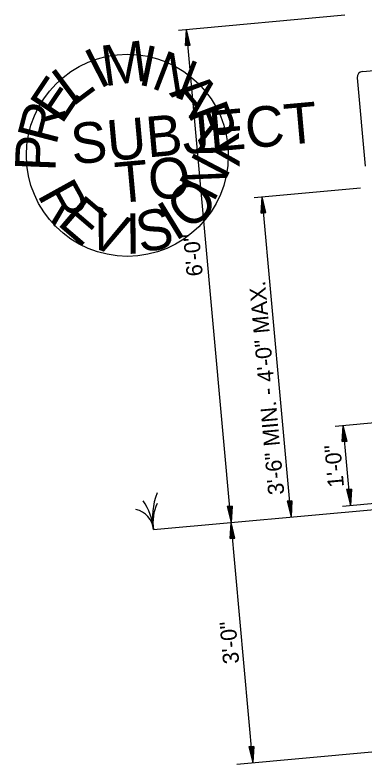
# Model space of a CAD drawing. Extents: x 1277218 to 1279252, y 196860 to 197529.
# Drawn here: x 1278236.5 to 1278336.3, y 197239.4 to 197453.2 of the extents above; entities that cross this region are included whole.
import ezdxf

# ---------------------------------------------------------------- set-up
doc = ezdxf.new("R2010")
doc.units = 0
doc.layers.add('R_Border PE', color=7, linetype='Continuous')
doc.layers.add('R_Point Sym', color=7, linetype='Continuous')

msp = doc.modelspace()

# ---------------------------------------------------------------- linework, layer by layer
at = {"layer": 'R_Border PE'}
msp.add_circle((1278268.61, 197413.17), 28.85, dxfattribs=at)
at = {"layer": 'R_Point Sym'}
for p, q in [((1278283.2, 197448.93), (1278330.8, 197453.24)), ((1278285.22, 197444.5), (1278285.49, 197449.13)), ((1278285.33, 197444.51), (1278285.56, 197448.37)), ((1278285.45, 197444.52), (1278285.63, 197447.58)), ((1278298.25, 197308.34), (1278285.49, 197449.13)), ((1278286.59, 197444.62), (1278285.49, 197449.13)), ((1278286.48, 197444.61), (1278285.56, 197448.37)), ((1278286.36, 197444.6), (1278285.63, 197447.58)), ((1278285.56, 197444.53), (1278285.7, 197446.82)), ((1278285.68, 197444.54), (1278285.77, 197446.05)), ((1278286.24, 197444.59), (1278285.7, 197446.82)), ((1278286.13, 197444.58), (1278285.77, 197446.05)), ((1278285.22, 197444.5), (1278286.59, 197444.62)), ((1278285.8, 197444.55), (1278285.84, 197445.28)), ((1278286.01, 197444.57), (1278285.84, 197445.28)), ((1278335.79, 197437.1), (1278349.6, 197438.36)), ((1278334.27, 197435.29), (1278336.56, 197410.05)), ((1278304.82, 197401.11), (1278335.28, 197403.87)), ((1278306.83, 197396.69), (1278307.11, 197401.32)), ((1278306.95, 197396.7), (1278307.17, 197400.56)), ((1278315.39, 197309.9), (1278307.11, 197401.32)), ((1278308.2, 197396.81), (1278307.11, 197401.32)), ((1278308.09, 197396.8), (1278307.17, 197400.56)), ((1278307.06, 197396.71), (1278307.25, 197399.77)), ((1278307.18, 197396.72), (1278307.31, 197399.01)), ((1278307.97, 197396.79), (1278307.25, 197399.77)), ((1278307.86, 197396.78), (1278307.31, 197399.01)), ((1278306.83, 197396.69), (1278308.2, 197396.81)), ((1278307.3, 197396.73), (1278307.38, 197398.24)), ((1278307.74, 197396.77), (1278307.38, 197398.24)), ((1278307.41, 197396.74), (1278307.45, 197397.47)), ((1278307.63, 197396.76), (1278307.45, 197397.47)), ((1278328.02, 197335.85), (1278341.33, 197337.06)), ((1278330.03, 197331.42), (1278330.3, 197336.06)), ((1278330.14, 197331.43), (1278330.37, 197335.29)), ((1278330.26, 197331.44), (1278330.44, 197334.51)), ((1278332.37, 197313.2), (1278330.3, 197336.06)), ((1278331.4, 197331.55), (1278330.3, 197336.06)), ((1278331.29, 197331.54), (1278330.37, 197335.29)), ((1278331.17, 197331.53), (1278330.44, 197334.51)), ((1278330.38, 197331.45), (1278330.51, 197333.75)), ((1278330.49, 197331.46), (1278330.58, 197332.97)), ((1278331.06, 197331.52), (1278330.51, 197333.75)), ((1278330.94, 197331.5), (1278330.58, 197332.97)), ((1278330.61, 197331.47), (1278330.65, 197332.21)), ((1278330.82, 197331.49), (1278330.65, 197332.21)), ((1278330.03, 197331.42), (1278331.4, 197331.55)), ((1278276.09, 197306.34), (1278517.66, 197328.23)), ((1278332.64, 197317.83), (1278331.27, 197317.71)), ((1278331.27, 197317.71), (1278332.37, 197313.2)), ((1278331.39, 197317.72), (1278332.3, 197313.96)), ((1278331.5, 197317.73), (1278332.23, 197314.75)), ((1278331.62, 197317.74), (1278332.16, 197315.51)), ((1278331.74, 197317.75), (1278332.09, 197316.29)), ((1278331.85, 197317.76), (1278332.02, 197317.05)), ((1278332.07, 197317.78), (1278332.02, 197317.05)), ((1278332.18, 197317.79), (1278332.09, 197316.29)), ((1278332.3, 197317.8), (1278332.16, 197315.51)), ((1278332.41, 197317.81), (1278332.23, 197314.75)), ((1278332.53, 197317.82), (1278332.3, 197313.96)), ((1278332.64, 197317.83), (1278332.37, 197313.2)), ((1278298.52, 197312.98), (1278297.15, 197312.85)), ((1278297.15, 197312.85), (1278298.25, 197308.34)), ((1278297.26, 197312.86), (1278298.18, 197309.11)), ((1278297.38, 197312.87), (1278298.11, 197309.89)), ((1278297.49, 197312.88), (1278298.04, 197310.66)), ((1278297.61, 197312.9), (1278297.97, 197311.43)), ((1278297.73, 197312.91), (1278297.9, 197312.19)), ((1278297.94, 197312.93), (1278297.9, 197312.19)), ((1278298.06, 197312.94), (1278297.97, 197311.43)), ((1278298.17, 197312.95), (1278298.04, 197310.66)), ((1278298.29, 197312.96), (1278298.11, 197309.89)), ((1278298.4, 197312.97), (1278298.18, 197309.11)), ((1278298.52, 197312.98), (1278298.25, 197308.34)), ((1278315.66, 197314.53), (1278314.29, 197314.41)), ((1278314.29, 197314.41), (1278315.39, 197309.9)), ((1278314.4, 197314.42), (1278315.32, 197310.66)), ((1278314.52, 197314.43), (1278315.25, 197311.45)), ((1278314.63, 197314.44), (1278315.18, 197312.21)), ((1278314.75, 197314.45), (1278315.11, 197312.98)), ((1278314.87, 197314.46), (1278315.04, 197313.75)), ((1278315.08, 197314.48), (1278315.04, 197313.75)), ((1278315.2, 197314.49), (1278315.11, 197312.98)), ((1278315.32, 197314.5), (1278315.18, 197312.21)), ((1278315.43, 197314.51), (1278315.25, 197311.45)), ((1278315.55, 197314.52), (1278315.32, 197310.66)), ((1278315.66, 197314.53), (1278315.39, 197309.9)), ((1278330.09, 197312.99), (1278343.4, 197314.2)), ((1278297.98, 197303.71), (1278298.25, 197308.34)), ((1278298.09, 197303.72), (1278298.32, 197307.58)), ((1278298.21, 197303.73), (1278298.39, 197306.79)), ((1278304.46, 197239.78), (1278298.25, 197308.34)), ((1278299.35, 197303.84), (1278298.25, 197308.34)), ((1278299.23, 197303.83), (1278298.32, 197307.58)), ((1278299.12, 197303.81), (1278298.39, 197306.79)), ((1278298.32, 197303.74), (1278298.46, 197306.03)), ((1278298.44, 197303.75), (1278298.53, 197305.26)), ((1278299, 197303.8), (1278298.46, 197306.03)), ((1278298.89, 197303.79), (1278298.53, 197305.26)), ((1278298.55, 197303.76), (1278298.6, 197304.5)), ((1278298.77, 197303.78), (1278298.6, 197304.5)), ((1278297.98, 197303.71), (1278299.35, 197303.84)), ((1278304.73, 197244.41), (1278303.36, 197244.29)), ((1278303.36, 197244.29), (1278304.46, 197239.78)), ((1278303.48, 197244.3), (1278304.39, 197240.54)), ((1278303.59, 197244.31), (1278304.32, 197241.33)), ((1278303.71, 197244.32), (1278304.25, 197242.09)), ((1278303.82, 197244.33), (1278304.18, 197242.86)), ((1278303.94, 197244.34), (1278304.11, 197243.63)), ((1278304.15, 197244.36), (1278304.11, 197243.63)), ((1278304.27, 197244.37), (1278304.18, 197242.86)), ((1278304.39, 197244.38), (1278304.25, 197242.09)), ((1278304.5, 197244.39), (1278304.32, 197241.33)), ((1278304.62, 197244.4), (1278304.39, 197240.54)), ((1278304.73, 197244.41), (1278304.46, 197239.78)), ((1278299.89, 197239.36), (1278338.46, 197242.86))]:
    msp.add_line(p, q, dxfattribs=at)
for centre, radius, start, end in [((1278335.94, 197435.44), 1.67, 95.1779, 185.1779), ((1278295.11, 197309.76), 19.33, 158.7815, 190.1949), ((1278258.61, 197304.63), 17.56, 5.5849, 34.4073), ((1278288.13, 197308.43), 12.22, 154.3228, 189.8496), ((1278269.48, 197305.62), 6.65, 6.1895, 76.3919)]:
    msp.add_arc(centre, radius, start, end, dxfattribs=at)

# ---------------------------------------------------------------- texts
at = {"layer": 'R_Border PE'}
for s, height, rotation, p in [('M', 11.6, 7.8722, (1278261.98, 197432.83)), ('I', 11.6, 27.1884, (1278260.61, 197431.97)), ('I', 11.6, 348.556, (1278271.29, 197433.43)), ('N', 11.6, 338.8978, (1278275.03, 197432.53)), ('L', 11.6, 36.8465, (1278252.94, 197426.9)), ('E', 11.6, 56.1628, (1278249.81, 197421.73)), ('A', 11.6, 309.9235, (1278280.4, 197430.83)), ('SUBJECT', 11.603, 5.1779, (1278252.95, 197410.59)), ('R', 11.6, 290.6072, (1278285.68, 197425.68)), ('R', 11.6, 75.479, (1278248.23, 197415.77)), ('P', 11.6, 87.7868, (1278248.02, 197408.43)), ('Y', 11.6, 271.291, (1278288.87, 197419.67)), ('N', 11.6, 62.3156, (1278293.22, 197399.47)), ('TO', 11.603, 5.1779, (1278265.61, 197399.49)), ('R', 11.6, 298.9418, (1278242.68, 197401.89)), ('O', 11.6, 41.7533, (1278286.31, 197391.24)), ('E', 11.6, 319.5041, (1278248.22, 197393.55)), ('V', 11.6, 340.0664, (1278256.33, 197387.67)), ('I', 11.6, 31.4722, (1278282.22, 197388.48)), ('I', 11.6, 0.6287, (1278268.13, 197385.02)), ('S', 11.6, 10.9099, (1278272.29, 197385.22))]:
    msp.add_text(s, height=height, rotation=rotation, dxfattribs=at).set_placement(p)
at = {"layer": 'R_Point Sym'}
for s, height, p in [('6\'-0"', 4.59, (1278290.18, 197378.82)), ('3\'-6" MIN. - 4\'-0" MAX.', 4.5899, (1278313.48, 197316.42)), ('1\'-0"', 4.59, (1278330.54, 197318.54)), ('3\'-0"', 4.59, (1278300.59, 197268.14))]:
    msp.add_text(s, height=height, rotation=95.1779, dxfattribs=at).set_placement(p)

doc.saveas('drawing.dxf')
